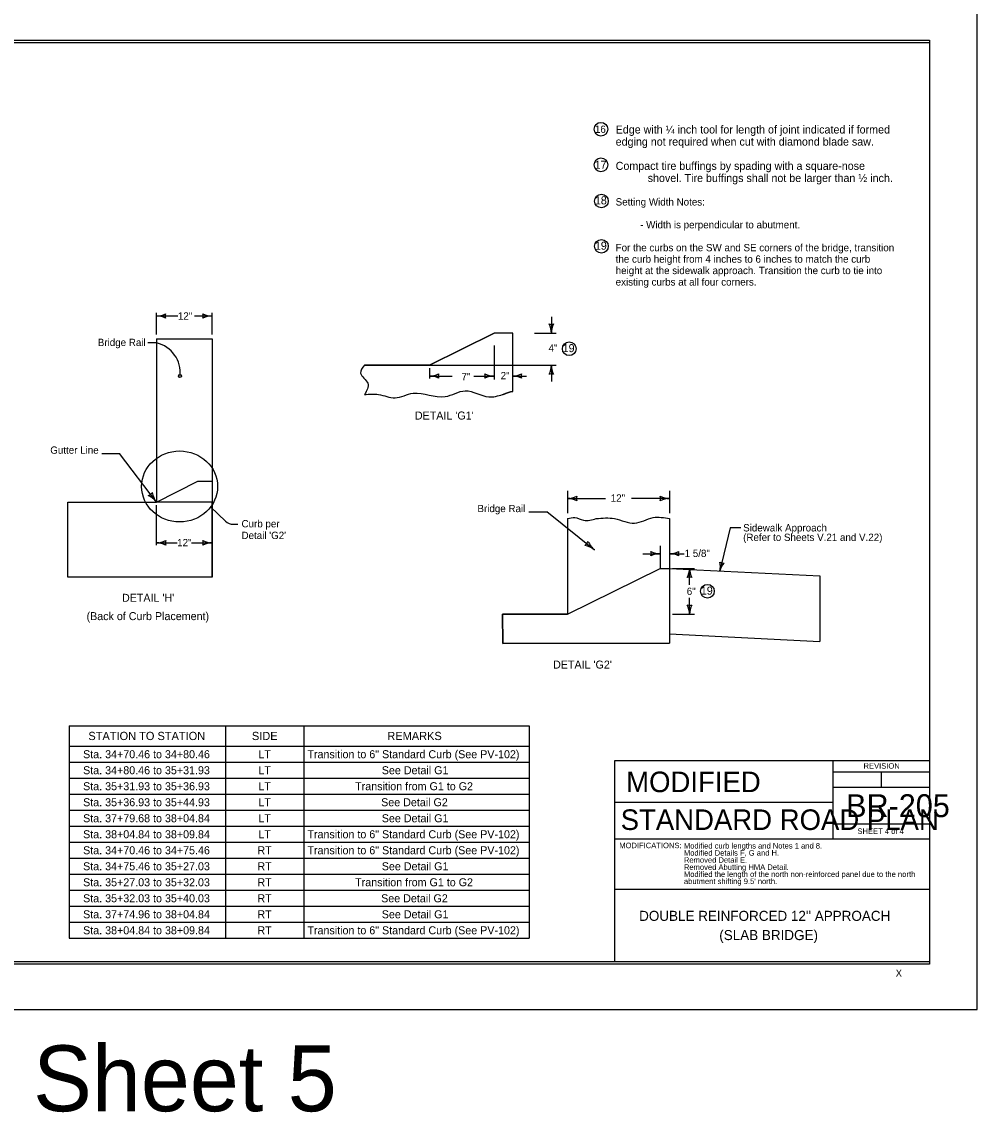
# Model space of a CAD drawing. Extents: x 10028 to 81668, y 6395 to 11634.
# Drawn here: x 25683 to 27772, y 7600 to 9984 of the extents above; entities that cross this region are included whole.
import ezdxf

# ---------------------------------------------------------------- set-up
doc = ezdxf.new("R2010")
doc.units = 0
for name, color, linetype in [('Constructions', 7, 'Continuous'), ('Default', 7, 'Continuous'), ('dsnCellElements', 7, 'Continuous'), ('dsnPaintPlaceStopLineWhite', 7, 'Continuous'), ('dsnstdblockInterim', 7, 'Continuous'), ('dsnStdBlockNotModified', 7, 'Continuous'), ('dsnStdDimension', 7, 'Continuous'), ('dsnStdTextLabel', 7, 'Continuous'), ('dsnTextNote', 7, 'Continuous'), ('ShtPlotIdentification', 7, 'Continuous'), ('TextAlignmentSml', 7, 'Continuous')]:
    doc.layers.add(name, color=color, linetype=linetype)

msp = doc.modelspace()

# ---------------------------------------------------------------- linework, layer by layer
at = {"layer": 'Default'}
msp.add_lwpolyline([(24532.5, 9944), (27667.6, 9944), (27667.6, 7924), (24532.5, 7924)], close=True, dxfattribs=at)
at = {"layer": 'dsnCellElements'}
for p, q in [((27232.3, 8877.9), (27209.5, 8783.6)), ((27255.3, 8877.9), (27232.3, 8877.9))]:
    msp.add_line(p, q, dxfattribs=at)
at = {"layer": 'dsnstdblockInterim'}
msp.add_lwpolyline([(24532.5, 9939), (27667.5, 9939), (27667.5, 7929), (24532.5, 7929)], close=True, dxfattribs=at)
at = {"layer": 'dsnStdBlockNotModified'}
for centre, radius, start, end in [((25977.6, 9383.6), 42.5, 270, 298.0725), ((25977.6, 9298.6), 42.5, 61.9275, 90), ((26013.2, 9341.1), 16.4, 162.2666, 197.7334), ((26063.5, 9341.1), 16.4, 342.2666, 17.7333), ((26099.2, 9383.6), 42.5, 241.9275, 270), ((26099.2, 9298.6), 42.5, 90, 118.0725), ((26841.1, 9339.2), 16.4, 252.2666, 287.7333), ((26798.6, 9303.6), 42.5, 360, 28.0725), ((26883.6, 9303.6), 42.5, 151.9275, 180), ((26798.6, 9233.7), 42.5, 331.9275, 360), ((26883.6, 9233.7), 42.5, 180, 208.0725), ((26574.6, 9252.3), 42.5, 270, 298.0725), ((26574.6, 9167.3), 42.5, 61.9275, 90), ((26610.2, 9209.8), 16.4, 162.2666, 197.7334), ((26680, 9209.8), 16.4, 342.2666, 17.7333), ((26715.7, 9252.3), 42.5, 241.9275, 270), ((26715.7, 9167.3), 42.5, 90, 118.0725), ((26841.1, 9198), 16.4, 72.2666, 107.7334), ((26876.6, 8984.5), 42.5, 270, 298.0725), ((26876.6, 8899.5), 42.5, 61.9275, 90), ((26912.2, 8942), 16.4, 162.2666, 197.7334), ((27063.6, 8942), 16.4, 342.2667, 17.7334), ((27099.3, 8984.5), 42.5, 241.9275, 270), ((27099.3, 8899.5), 42.5, 90, 118.0725), ((25977.8, 8887.5), 42.5, 270, 298.0725), ((26013.5, 8845), 16.4, 162.2666, 197.7334), ((26063.5, 8845), 16.4, 342.2666, 17.7333), ((26099.2, 8887.5), 42.5, 241.9275, 270), ((25977.8, 8802.5), 42.5, 61.9275, 90), ((26099.2, 8802.5), 42.5, 90, 118.0725), ((27043.3, 8821.3), 16.4, 342.2666, 17.7333), ((27078.9, 8863.8), 42.5, 241.9275, 270), ((27099.3, 8863.8), 42.5, 270, 298.0725), ((27134.9, 8821.3), 16.4, 162.2666, 197.7334), ((27078.9, 8778.8), 42.5, 90, 118.0725), ((27099.3, 8778.8), 42.5, 61.9275, 90), ((27100.7, 8789.1), 42.5, 331.9275, 0), ((27185.7, 8789.1), 42.5, 180, 208.0725), ((27143.2, 8753.5), 16.4, 72.2666, 107.7334), ((27143.2, 8724.7), 16.4, 252.2666, 287.7334), ((27100.7, 8689), 42.5, 0, 28.0725), ((27185.7, 8689), 42.5, 151.9275, 180)]:
    msp.add_arc(centre, radius, start, end, dxfattribs=at)
at = {"layer": 'dsnStdDimension'}
msp.add_lwpolyline([(24428, 7824.5), (27772, 7824.5), (27772, 10408.5), (24428, 10408.5)], close=True, dxfattribs=at)
at = {"layer": 'ShtPlotIdentification'}
for p, q in [((25977.8, 9300.4), (25977.8, 9347.8)), ((26099.2, 9300.4), (26099.2, 9347.8)), ((25977.8, 9341.1), (26024.2, 9341.1)), ((26060.6, 9341.1), (26099.2, 9341.1)), ((26841.1, 9339.3), (26841.1, 9303.6)), ((26756.6, 9303.6), (26715.9, 9303.6)), ((26756.6, 9176.3), (26756.6, 9303.6)), ((26804, 9303.6), (26851.9, 9303.6)), ((25978.1, 9282.1), (25958.6, 9282.1)), ((25977.8, 9291.3), (26099.2, 9291.3)), ((25977.8, 9291.3), (25977.8, 8933.7)), ((26715.7, 9276.2), (26715.7, 9202.4)), ((26456.8, 9233.6), (26432.4, 9233.6)), ((26573.4, 9233.6), (26432.4, 9233.6)), ((26432.7, 9233.6), (26478.6, 9233.6)), ((26478.6, 9233.6), (26456.8, 9233.6)), ((26574.5, 9233.6), (26478.6, 9233.6)), ((26478.6, 9233.6), (26574.5, 9233.6)), ((26574.6, 9233.6), (26573.4, 9233.6)), ((26574.5, 9233.6), (26851.9, 9233.7)), ((26841.1, 9233.7), (26841.1, 9198)), ((26574.5, 9227.3), (26574.5, 9204.3)), ((26574.6, 9209.8), (26624, 9209.8)), ((26671.6, 9209.8), (26715.7, 9209.8)), ((26756.6, 9209.8), (26787, 9209.8)), ((25858.4, 9040.5), (25897.3, 9040.5)), ((25977.8, 8933.7), (25897.3, 9040.5)), ((25977.8, 8933.7), (26068.1, 8980.2)), ((26068.1, 8980.2), (26099.2, 8980.2)), ((26068.1, 8980.2), (26099.2, 8980.2)), ((26099.2, 8980.2), (26099.2, 8769.6)), ((26876.6, 8958.8), (26876.6, 8909.8)), ((26876.6, 8942), (26959.4, 8942)), ((27099.3, 8942), (27016.4, 8942)), ((27099.3, 8958.8), (27099.3, 8909.8)), ((26068.1, 8933.7), (25977.8, 8933.7)), ((25977.8, 8839.8), (25977.8, 8927.2)), ((26096.1, 8923.4), (26128.9, 8892.5)), ((26099.2, 8769.6), (26099.2, 8933.6)), ((26099.2, 8839.8), (26099.2, 8927.2)), ((26792.2, 8912.8), (26831.2, 8912.8)), ((26935.7, 8829.3), (26831.2, 8912.8)), ((26876.6, 8898), (26876.6, 8689)), ((27099.3, 8898), (27099.3, 8827.8)), ((26146, 8885.7), (26155.9, 8885.7)), ((25977.8, 8845), (26023, 8845)), ((26054.5, 8845), (26099.2, 8845)), ((27078.9, 8838.1), (27078.9, 8789.1)), ((27099.3, 8827.8), (27099.3, 8625.9)), ((27041.2, 8821.3), (27078.9, 8821.3)), ((27099.3, 8821.3), (27131.5, 8821.3)), ((26876.6, 8689), (27078.9, 8789.1)), ((27078.9, 8789.1), (27099.3, 8789.1)), ((27099.3, 8789.1), (27428.4, 8772.5)), ((27106.1, 8789.1), (27154, 8789.1)), ((27143.2, 8753.4), (27143.2, 8789.1)), ((27428.4, 8772.5), (27428.4, 8629.6)), ((27143.2, 8689), (27143.2, 8724.8)), ((26875.5, 8689), (26734.5, 8689)), ((26734.5, 8689), (26734.7, 8624.7)), ((26876.7, 8689), (26875.5, 8689)), ((27105.9, 8689), (27154, 8689)), ((27099.3, 8646.3), (27428.4, 8629.6)), ((26734.7, 8624.7), (27099.3, 8625.9)), ((25786.8, 8445.2), (26792.8, 8445.2)), ((25786.8, 8445.2), (25786.8, 7980.2)), ((26128.5, 8445.2), (26128.5, 7980.2)), ((26299.9, 8445.2), (26299.9, 7980.2)), ((26792.8, 8445.2), (26792.8, 7980.2)), ((25786.8, 8400.2), (26792.8, 8400.2)), ((25786.8, 8365.2), (26792.8, 8365.2)), ((25786.8, 8330.2), (26792.8, 8330.2)), ((25786.8, 8295.2), (26792.8, 8295.2)), ((25786.8, 8260.2), (26792.8, 8260.2)), ((25786.8, 8225.2), (26792.8, 8225.2)), ((25786.8, 8190.2), (26792.8, 8190.2)), ((25786.8, 8155.2), (26792.8, 8155.2)), ((25786.8, 8120.2), (26792.8, 8120.2)), ((25786.8, 8085.2), (26792.8, 8085.2)), ((25786.8, 8050.2), (26792.8, 8050.2)), ((25786.8, 8015.2), (26792.8, 8015.2)), ((25786.8, 7980.2), (26792.8, 7980.2))]:
    msp.add_line(p, q, dxfattribs=at)
for points in [[(26715.9, 9303.6), (26574.6, 9233.6), (26574.5, 9233.6)], [(26574.5, 9233.6), (26715.9, 9303.6)], [(26756.6, 9303.6), (26734.6, 9303.6), (26715.9, 9303.6)], [(26756.6, 9176.3), (26756.6, 9176.3), (26756.6, 9303.6)], [(26099.2, 9291.3), (26099.2, 8933.6), (26068.1, 8933.7)], [(25977.8, 8933.7), (26068.1, 8980.2)], [(26099.2, 8769.6), (25783.8, 8769.6), (25783.8, 8933.7), (25929.8, 8933.7), (25977.8, 8933.7)], [(26099.2, 8769.6), (25783.8, 8769.6), (25783.8, 8933.7), (25929.8, 8933.7), (25977.8, 8933.7)]]:
    msp.add_lwpolyline(points, dxfattribs=at)
msp.add_lwpolyline([(26734.5, 8689), (26876.1, 8689), (26876.6, 8689), (27078.9, 8789.1), (27099.3, 8789.1), (27099.3, 8625.9), (26734.7, 8624.7)], close=True, dxfattribs=at)
for centre, radius in [((26949.6, 9749.4), 15), ((26949.6, 9671.6), 15), ((26950.5, 9592.5), 15), ((26950.5, 9493.4), 15), ((26880.1, 9269.3), 15), ((26029.2, 9209.8), 3.32), ((27182.2, 8739.1), 15)]:
    msp.add_circle(centre, radius, dxfattribs=at)
for centre, radius, start, end in [((25963, 9217.2), 66.7, 353.5756, 76.8823), ((26756.6, 9250.1), 40.3, 270, 298.0725), ((26756.6, 9169.5), 40.3, 61.9275, 90), ((26790.4, 9209.8), 15.6, 162.2666, 197.7334), ((25953.5, 8966.1), 18.7, 289.2015, 324.6682), ((25939.2, 8904.6), 48.4, 36.9348, 65.0073), ((26016.5, 8962.8), 48.4, 188.8623, 216.9348), ((26146, 8910.7), 25, 226.7172, 270), ((26904.1, 8854.9), 18.7, 303.2377, 338.7044), ((26966.1, 8866.9), 48.4, 202.8986, 230.9711), ((26905.2, 8791.8), 48.4, 50.9711, 79.0436), ((27217.4, 8816.3), 15.5, 238.7255, 274.1922), ((27170.4, 8793), 40.2, 346.4588, 14.5313), ((27248.5, 8774.2), 40.2, 138.3863, 166.4588)]:
    msp.add_arc(centre, radius, start, end, dxfattribs=at)
msp.add_ellipse((26028.4, 8968.3), major_axis=(83, 0), ratio=0.93542, dxfattribs=at)
for points in [[(26432.4, 9233.6), (26424.1, 9216), (26439.9, 9193.8), (26432.7, 9169.3)], [(26432.4, 9233.6), (26424.1, 9216), (26439.9, 9193.8), (26432.7, 9169.3)], [(26432.7, 9169.3), (26463.2, 9169.3), (26499.4, 9162.3), (26539, 9172.2), (26609, 9164.7), (26652.8, 9177.5), (26704.1, 9164.1), (26734.6, 9169.3)], [(26432.7, 9169.3), (26463.2, 9169.3), (26499.4, 9162.3), (26539, 9172.2), (26609, 9164.7), (26652.8, 9177.5), (26704.1, 9164.1), (26734.6, 9169.3)], [(26734.6, 9169.3), (26748.7, 9174.4), (26754, 9175.9)], [(26876.6, 8898), (26892.3, 8900.5), (26911.3, 8894.6), (26939.2, 8898)], [(26939.2, 8898), (26979.3, 8898), (27023.1, 8888), (27063.9, 8900.2), (27099.3, 8898)]]:
    msp.add_spline(points, degree=3, dxfattribs=at)
msp.add_open_spline([(26734.6, 9169.3), (26735.5, 9169.6), (26736.4, 9169.9), (26737.3, 9170.2), (26738.3, 9170.5), (26739.2, 9170.9), (26740.1, 9171.2), (26741.9, 9171.9), (26743.8, 9172.7), (26745.6, 9173.4), (26747.4, 9174.1), (26749.2, 9174.7), (26751.1, 9175.2), (26752, 9175.5), (26752.9, 9175.7), (26753.8, 9175.9), (26754.3, 9176), (26754.7, 9176.1), (26755.2, 9176.1), (26755.6, 9176.2), (26756.1, 9176.3), (26756.6, 9176.3)], degree=3, dxfattribs=at)
at = {"layer": 'TextAlignmentSml'}
for p, q in [((27456.6, 8369), (27456.6, 8277.7)), ((27456.6, 8344.1), (27667.5, 8344.1)), ((27562.1, 8344.1), (27562.1, 8310.9)), ((27456.6, 8310.9), (27667.5, 8310.9)), ((26979.5, 8277.7), (27456.6, 8277.7)), ((27456.6, 8277.7), (27456.6, 8197.7)), ((27667.5, 8229.9), (27456.6, 8229.9)), ((26979.5, 8197.7), (27667.5, 8197.7)), ((26979.5, 8087.7), (27667.5, 8087.7))]:
    msp.add_line(p, q, dxfattribs=at)
msp.add_lwpolyline([(26979.5, 8369), (27667.5, 8369), (27667.5, 7929), (26979.5, 7929)], close=True, dxfattribs=at)

# ---------------------------------------------------------------- texts
at = {"layer": 'Constructions'}
msp.add_text('X', height=16, dxfattribs=at).set_placement((27593.6, 7896))
at = {"layer": 'dsnCellElements'}
for s, height, p in [('17', 17.5, (26935.6, 9662.9)), ('18', 17.5, (26936.2, 9585.1)), ('19', 17.5, (26936.2, 9486)), ('19', 17.5, (26865.8, 9262)), ('Sidewalk Approach', 16, (27260.4, 8869.9)), ('(Refer to Sheets V.21 and V.22)', 16, (27260.4, 8849.1)), ('19', 17.5, (27167.9, 8731.7)), ('(Back of Curb Placement)', 17.5, (25824.9, 8676))]:
    msp.add_text(s, height=height, dxfattribs=at).set_placement(p)
at = {"layer": 'dsnPaintPlaceStopLineWhite'}
for s, height, p in [('16', 16, (26936.3, 9741.4)), ('Edge with ¼ inch tool for length of joint indicated if formed ', 17.5, (26981.7, 9740.1)), ('edging not required when cut with diamond blade saw.', 17.5, (26981.7, 9713.6)), ('Compact tire buffings by spading with a square-nose ', 17.5, (26981.7, 9660.6)), ('shovel. Tire buffings shall not be larger than ½ inch.', 17.5, (27051.7, 9634.1)), ('Setting Width Notes:', 16, (26981.7, 9582.6)), ('         - Width is perpendicular to abutment.', 16, (26981.7, 9532.6)), ('For the curbs on the SW and SE corners of the bridge, transition ', 16, (26981.7, 9482.6)), ('the curb height from 4 inches to 6 inches to match the curb ', 16, (26981.7, 9457.6)), ('height at the sidewalk approach. Transition the curb to tie into ', 16, (26981.7, 9432.6)), ('existing curbs at all four corners.', 16, (26981.7, 9407.6))]:
    msp.add_text(s, height=height, dxfattribs=at).set_placement(p)
at = {"layer": 'dsnStdTextLabel'}
msp.add_text('Sheet 5', height=144, dxfattribs=at).set_placement((25708.1, 7602))
at = {"layer": 'dsnTextNote'}
for s, height, p in [('MODIFIED', 45, (27004.6, 8299.8)), ('MODIFICATIONS:', 12, (26989.5, 8177.3))]:
    msp.add_text(s, height=height, dxfattribs=at).set_placement(p)
at = {"layer": 'ShtPlotIdentification'}
for s, height, p in [('12"', 16, (26024.6, 9333.1)), ('Bridge Rail', 16, (25849.5, 9275.3)), ('4"', 16, (26835, 9262.9)), ('7"', 16, (26644.7, 9200.6)), ('2"', 16, (26730.2, 9202.7)), ("DETAIL 'G1'", 17.5, (26542.7, 9114.6)), ('Gutter Line', 16, (25745.6, 9039.8)), ('12"', 16, (26970.9, 8935.1)), ('Bridge Rail', 16, (26679.5, 8912.1)), ('Curb per', 16, (26163.7, 8878.8)), ("Detail 'G2'", 16, (26163.7, 8853.3)), ('12"', 16, (26023, 8837.5)), ('1 5/8"', 16, (27132.5, 8814.1)), ("DETAIL 'H'", 17.5, (25902.4, 8716)), ('6"', 16, (27137.1, 8731)), ("DETAIL 'G2'", 17.5, (26844.8, 8570)), ('STATION TO STATION', 18, (25828.9, 8413.7)), ('SIDE', 18, (26186.4, 8413.7)), ('REMARKS', 18, (26482.5, 8413.7)), ('Sta. 34+70.46 to 34+80.46', 17.5, (25817.4, 8374)), ('LT', 17.5, (26200.5, 8374)), ('Transition to 6" Standard Curb (See PV-102)', 17.5, (26307.8, 8374)), ('Sta. 34+80.46 to 35+31.93', 17.5, (25817.4, 8339)), ('LT', 17.5, (26200.5, 8339)), ('See Detail G1', 17.5, (26470.4, 8339)), ('Sta. 35+31.93 to 35+36.93', 17.5, (25817.4, 8304)), ('Transition from G1 to G2', 17.5, (26412.2, 8304)), ('LT', 17.5, (26200.5, 8304)), ('Sta. 35+36.93 to 35+44.93', 17.5, (25817.4, 8269)), ('LT', 17.5, (26200.5, 8269)), ('See Detail G2', 17.5, (26469, 8269)), ('Sta. 37+79.68 to 38+04.84', 17.5, (25817.4, 8234)), ('LT', 17.5, (26200.5, 8234)), ('See Detail G1', 17.5, (26470.4, 8234)), ('Sta. 38+04.84 to 38+09.84', 17.5, (25817.4, 8199)), ('LT', 17.5, (26200.5, 8199)), ('Transition to 6" Standard Curb (See PV-102)', 17.5, (26307.8, 8199)), ('Sta. 34+70.46 to 34+75.46', 17.5, (25817.4, 8164)), ('RT', 17.5, (26198.5, 8164)), ('Transition to 6" Standard Curb (See PV-102)', 17.5, (26307.8, 8164)), ('Sta. 34+75.46 to 35+27.03', 17.5, (25817.4, 8129)), ('RT', 17.5, (26198.5, 8129)), ('See Detail G1', 17.5, (26470.4, 8129)), ('Sta. 35+27.03 to 35+32.03', 17.5, (25817.4, 8094)), ('RT', 17.5, (26198.5, 8094)), ('Transition from G1 to G2', 17.5, (26412.2, 8094)), ('Sta. 35+32.03 to 35+40.03', 17.5, (25817.4, 8059)), ('RT', 17.5, (26198.5, 8059)), ('See Detail G2', 17.5, (26469, 8059)), ('Sta. 37+74.96 to 38+04.84', 17.5, (25817.4, 8024)), ('RT', 17.5, (26198.5, 8024)), ('See Detail G1', 17.5, (26470.4, 8024)), ('Sta. 38+04.84 to 38+09.84', 17.5, (25817.4, 7989)), ('RT', 17.5, (26198.5, 7989)), ('Transition to 6" Standard Curb (See PV-102)', 17.5, (26307.8, 7989))]:
    msp.add_text(s, height=height, dxfattribs=at).set_placement(p)
at = {"layer": 'TextAlignmentSml'}
for s, height, p in [('REVISION', 12, (27523.6, 8351.2)), ('BR-205', 50, (27485.5, 8245.2)), ('STANDARD ROAD PLAN', 45.001, (26992.6, 8217.1)), ('SHEET 4 of 4', 12, (27510.3, 8208.5)), ('Modified curb lengths and Notes 1 and 8.', 12, (27130.9, 8176.5)), ('Modified Details F, G and H.', 12, (27130.9, 8161)), ('Removed Detail E.', 12, (27130.9, 8145.5)), ('Removed Abutting HMA Detail.', 12, (27130.9, 8129.9)), ("abutment shifting 9.5' north.", 12, (27130.9, 8098.9)), ('Modified the length of the north non-reinforced panel due to the north', 12, (27130.9, 8114.4)), ("DOUBLE REINFORCED 12'' APPROACH", 22, (27033, 8018.3)), ('(SLAB BRIDGE)', 22, (27208.2, 7976.3))]:
    msp.add_text(s, height=height, dxfattribs=at).set_placement(p)

doc.saveas('drawing.dxf')
